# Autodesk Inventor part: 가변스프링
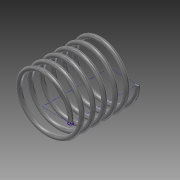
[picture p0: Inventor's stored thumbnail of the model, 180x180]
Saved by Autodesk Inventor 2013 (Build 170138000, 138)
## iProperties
Created: 2018-02
Part Number: 가변스프링
Material: 스테인리스강
Document SubType Name: Modeling
Designer: Administrator
Density: 8.08 g/cm^3
Mass: 42.4851 g
Surface Area: 70.86 cm^2
Volume: 5.25806 cm^3
Author: Administrator
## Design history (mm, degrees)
sketch "스케치1"
  geometry: L1 (0, 0)-(20, 0); L2 (20, 0)-(20, 47.25); L3 (20, 47.25)-(0, 47.25); L4 (0, 47.25)-(0, 0); C1 r 1.5 at (20, 0)
  constraints: 8 end point, 2 parallel, 1 centre point, 1 coincident, 1 horizontal, 1 perpendicular
  dimensions: "d0" = 40 diameter of L2 L4; "d2" = 47.25 distance of L1.end L2.end (derived); "d3" = 3 diameter of C1
feature "코일1" pitch "d4" = 10; turns "d6" = 6; dims "d5" = 47.25 (= d2), "d7" = 0, angle "d8" = 90 deg, angle "d9" = 90 deg, "d10" = 0, "d11" = 0
sketch "스케치2"
  geometry: L1 (-18.5, 0)-(-21.5, 0) reference; 1 further point
  constraints: 1 horizontal alignment
extrude "돌출1" cut sketch "스케치2" stored distance "d12" = 10; taper "d13" = 0 deg
node "작업 평면1"
sketch "스케치3"
  geometry: L1 (-1.5, 0)-(1.5, 0) reference; 1 further point
  constraints: 1 horizontal alignment
extrude "돌출2" cut sketch "스케치3" stored distance "d14" = 10; taper "d15" = 0 deg
node "솔리드1"
node "절단 모서리 투영1"
node "절단 모서리 투영2"
